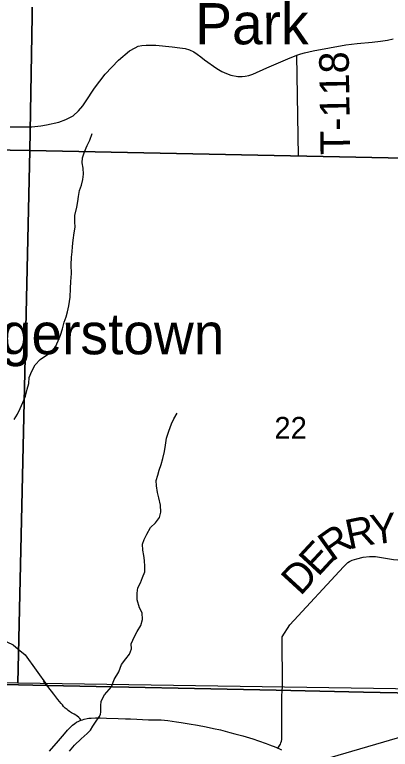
# Model space of a CAD drawing. Extents: x -7.1 to 34, y 0 to 22.
# Drawn here: x 5.689 to 6.409, y 17.646 to 19.056 of the extents above; entities that cross this region are included whole.
import ezdxf

# ---------------------------------------------------------------- set-up
doc = ezdxf.new("R2010")
doc.units = 0
for name, color, linetype in [('GM_X_Minor_River', 7, 'Continuous'), ('GM_X_Section', 7, 'Continuous'), ('GM_X_Section_Text', 7, 'Continuous'), ('GM_X_State_Route', 7, 'Continuous'), ('GM_X_Township_Road', 7, 'Continuous'), ('GM_X_Township_Road_Text', 7, 'Continuous'), ('GM_X_Unincorporated_Text', 7, 'Continuous'), ('SH_Cut_Line', 7, 'Continuous'), ('SH_Text', 7, 'Continuous')]:
    doc.layers.add(name, color=color, linetype=linetype)

msp = doc.modelspace()

# ---------------------------------------------------------------- linework, layer by layer
at = {"layer": 'GM_X_Minor_River'}
for points in [[(5.7952, 18.5136), (5.7962, 18.5303), (5.7965, 18.5436), (5.7979, 18.5588), (5.7974, 18.5755), (5.798, 18.5907), (5.7991, 18.6006), (5.8001, 18.6112), (5.8011, 18.623), (5.8033, 18.6371), (5.8051, 18.6481), (5.8046, 18.6583), (5.8045, 18.6701), (5.8082, 18.6865), (5.8104, 18.6971), (5.8114, 18.707), (5.8136, 18.7184), (5.817, 18.7287), (5.8195, 18.7397), (5.8213, 18.75), (5.8201, 18.761), (5.8185, 18.7716), (5.8192, 18.7814), (5.8229, 18.7925), (5.8281, 18.8047), (5.8329, 18.815), (5.8378, 18.8279)], [(5.6878, 18.2785), (5.6942, 18.2892), (5.6998, 18.3002), (5.7046, 18.3117), (5.7098, 18.3239), (5.7128, 18.3372), (5.7161, 18.3482), (5.7171, 18.3592), (5.722, 18.3718), (5.7283, 18.3836), (5.7377, 18.3939), (5.7479, 18.4009), (5.7593, 18.4078), (5.7675, 18.4185), (5.7724, 18.4299), (5.7772, 18.4406), (5.7805, 18.4528), (5.7839, 18.4657), (5.788, 18.476), (5.7902, 18.4855), (5.7927, 18.4973), (5.7952, 18.5136)], [(5.8747, 17.7657), (5.8797, 17.7794), (5.889, 17.7947), (5.8938, 17.8084), (5.9021, 17.8191), (5.9092, 17.8286), (5.913, 17.8385), (5.9121, 17.848), (5.9185, 17.8625), (5.9241, 17.872), (5.9312, 17.8835), (5.9341, 17.8949), (5.9333, 17.9074), (5.9286, 17.9176), (5.9239, 17.9328), (5.9238, 17.9457), (5.9249, 17.9559), (5.9305, 17.9655), (5.9338, 17.9757), (5.9383, 17.9864), (5.9386, 17.9967), (5.9377, 18.008), (5.9369, 18.0179), (5.9349, 18.0281), (5.9344, 18.0392), (5.9374, 18.0487), (5.9426, 18.059), (5.9497, 18.0712), (5.9588, 18.0807), (5.9667, 18.0907), (5.9692, 18.1009), (5.9688, 18.1146), (5.9656, 18.1283), (5.9629, 18.1389), (5.9608, 18.1514), (5.9604, 18.1616), (5.9633, 18.1719), (5.9663, 18.1814), (5.97, 18.1924), (5.9729, 18.2042), (5.9762, 18.2172), (5.9784, 18.2297), (5.9802, 18.243), (5.9843, 18.2563), (5.9899, 18.2708), (5.9943, 18.2804), (6.0007, 18.291)], [(5.7939, 17.6422), (5.8036, 17.6534), (5.8166, 17.6658), (5.8279, 17.6759), (5.8342, 17.6825), (5.8386, 17.6902), (5.8442, 17.6979), (5.8509, 17.7079), (5.8535, 17.7128), (5.8541, 17.7178), (5.8541, 17.7235), (5.8544, 17.7292), (5.855, 17.7384), (5.8611, 17.7502), (5.8747, 17.7657)]]:
    msp.add_lwpolyline(points, dxfattribs=at)
at = {"layer": 'GM_X_Section'}
for points in [[(4.7229, 19.8074), (5.7351, 19.7911), (5.7181, 18.7951), (4.6987, 18.8125)], [(6.7637, 19.7708), (6.7487, 18.7741), (5.7181, 18.7951), (5.7351, 19.7911)], [(4.6987, 18.8125), (5.7181, 18.7951), (5.6951, 17.7726), (4.6817, 17.7925)], [(5.7181, 18.7951), (6.7487, 18.7741), (6.7175, 17.7575), (5.6951, 17.7726)]]:
    msp.add_lwpolyline(points, close=True, dxfattribs=at)
at = {"layer": 'GM_X_State_Route'}
for points in [[(5.6805, 18.8406), (5.6895, 18.8408), (5.7085, 18.8405), (5.722, 18.8407), (5.7391, 18.8422), (5.7503, 18.8442), (5.774, 18.8494), (5.787, 18.8549), (5.801, 18.862), (5.8116, 18.8712), (5.8196, 18.8807), (5.8251, 18.8884), (5.8419, 18.9148), (5.8625, 18.942), (5.8878, 18.9683), (5.9091, 18.9862), (5.92, 18.9923), (5.9257, 18.9952), (5.9328, 18.9965), (5.9413, 18.9975), (5.9599, 18.9973), (5.9908, 18.9942), (6.0058, 18.9924), (6.0161, 18.9908), (6.0244, 18.9885), (6.0324, 18.9848), (6.0387, 18.9803), (6.046, 18.9747), (6.0532, 18.9692), (6.0765, 18.9524), (6.0861, 18.9467), (6.0949, 18.9429), (6.1037, 18.9397), (6.1171, 18.9371), (6.1253, 18.9373), (6.1312, 18.9378), (6.1376, 18.9392), (6.1454, 18.942), (6.1726, 18.9536), (6.2125, 18.9714), (6.2301, 18.9784), (6.2374, 18.9809), (6.2449, 18.9829), (6.2611, 18.9864), (6.3241, 18.998), (6.3453, 19.0008), (6.3746, 19.0033), (6.3905, 19.0051), (6.4036, 19.007), (6.4146, 19.0096)], [(5.7561, 17.6423), (5.773, 17.6619), (5.7848, 17.6756), (5.7906, 17.6822), (5.7938, 17.6858), (5.7976, 17.6897), (5.8002, 17.6921), (5.8042, 17.6952), (5.8079, 17.6977), (5.8119, 17.6996), (5.8148, 17.7009), (5.8168, 17.7017), (5.8189, 17.7024), (5.822, 17.7034), (5.8283, 17.7048), (5.831, 17.7052), (5.8359, 17.7056), (5.844, 17.7059), (5.8532, 17.706), (5.8648, 17.7058), (5.8872, 17.7051), (5.9014, 17.7045), (5.9112, 17.704), (5.9235, 17.7034), (5.9341, 17.7029), (5.9459, 17.7026), (5.9642, 17.7022), (5.9696, 17.702), (5.9764, 17.7015), (5.9827, 17.7009), (5.9992, 17.6986), (6.0079, 17.6973), (6.0237, 17.6947), (6.0398, 17.6918), (6.0559, 17.6888), (6.0703, 17.6859), (6.0839, 17.6828), (6.1017, 17.6783), (6.1113, 17.6757), (6.1263, 17.6714), (6.1458, 17.6656), (6.1563, 17.6621), (6.1713, 17.6569), (6.1776, 17.6546), (6.1898, 17.6497), (6.1936, 17.6481), (6.1954, 17.6472), (6.2003, 17.6448)]]:
    msp.add_lwpolyline(points, dxfattribs=at)
at = {"layer": 'GM_X_Township_Road'}
msp.add_line((6.2329, 18.7841), (6.2301, 18.9784), dxfattribs=at)
for points in [[(3.0659, 17.6986), (3.7215, 17.6707), (3.8238, 17.6717), (3.8304, 17.7952), (4.3, 17.7873), (4.5657, 17.7857), (4.7094, 17.7848), (5.0443, 17.7832), (5.0544, 17.7831), (5.1115, 17.7819), (5.5047, 17.7737), (5.7514, 17.7685), (6.1904, 17.7592), (6.3575, 17.7557), (6.7118, 17.7486), (6.7254, 18.1319), (6.7433, 18.7732), (6.7479, 19.0295), (6.7613, 19.7723), (6.7882, 20.743), (6.7921, 20.9), (2.1, 20.9)], [(5.2365, 18.4256), (5.2644, 18.3793), (5.303, 18.3221), (5.3322, 18.273), (5.3497, 18.2309), (5.3626, 18.2069), (5.3746, 18.1857), (5.4925, 18.0448), (5.6107, 17.9087), (5.6293, 17.8901), (5.6466, 17.8752), (5.6574, 17.8644), (5.6741, 17.8518), (5.6861, 17.8465), (5.6957, 17.8381), (5.7094, 17.8273), (5.7516, 17.7679)], [(6.2024, 17.7664), (6.2016, 17.8617), (6.2162, 17.8849), (6.3195, 17.9962), (6.3277, 18.004), (6.3307, 18.0063), (6.3357, 18.0086), (6.345, 18.0116), (6.3572, 18.0148), (6.3694, 18.0158), (6.3809, 18.0156), (6.4152, 18.0101), (6.4234, 18.0097), (6.4297, 18.0103), (6.5025, 18.0314), (6.5146, 18.0366), (6.552, 18.0589), (6.5663, 18.0667), (6.6032, 18.0731), (6.7016, 18.1184), (6.7052, 18.1201), (6.7079, 18.1213), (6.7121, 18.1237)], [(6.7058, 17.2839), (6.7118, 17.7486), (6.3575, 17.7557), (6.1904, 17.7592), (5.7514, 17.7685), (5.5047, 17.7737), (5.1115, 17.7819), (5.0544, 17.7831), (5.0443, 17.7832), (4.7094, 17.7848), (4.5657, 17.7857), (4.3, 17.7873), (3.8304, 17.7952), (3.8238, 17.6717), (3.7215, 17.6707), (3.0659, 17.6986), (2.7886, 17.7105), (2.5551, 17.7155), (2.1, 17.7253), (2.1, 14.1)], [(5.8168, 17.7017), (5.8139, 17.705), (5.8122, 17.7067), (5.8084, 17.7098), (5.8065, 17.7111), (5.8029, 17.7132), (5.7982, 17.7159), (5.7942, 17.7184), (5.7919, 17.72), (5.7895, 17.7219), (5.786, 17.7248), (5.7829, 17.7282), (5.7807, 17.731), (5.7782, 17.7339), (5.7753, 17.7375), (5.772, 17.7415), (5.764, 17.7513), (5.7527, 17.766), (5.7471, 17.7732), (5.7445, 17.7767)], [(6.1936, 17.6481), (6.1962, 17.652), (6.1984, 17.6559), (6.1994, 17.6581), (6.2004, 17.6614), (6.201, 17.6648), (6.2013, 17.6683), (6.2014, 17.6735), (6.2011, 17.7175), (6.2012, 17.7335), (6.2014, 17.7479), (6.2019, 17.758), (6.2024, 17.7664)]]:
    msp.add_lwpolyline(points, dxfattribs=at)
at = {"layer": 'SH_Cut_Line'}
for points in [[(8.9, 17.7079), (8.9, 20.9), (2.1, 20.9), (2.1, 17.7253), (2.5551, 17.7155), (2.7886, 17.7105), (3.0659, 17.6986), (3.7215, 17.6707), (3.8238, 17.6717), (3.8304, 17.7952), (4.3, 17.7873), (4.5657, 17.7857), (4.7094, 17.7848), (5.0443, 17.7832), (5.0544, 17.7831), (5.1115, 17.7819), (5.5047, 17.7737), (5.7514, 17.7685), (6.1904, 17.7592), (6.3575, 17.7557), (6.7118, 17.7486), (7.7202, 17.7285), (8.4472, 17.7189), (8.6668, 17.7136)], [(2.1, 17.7253), (2.1, 14.1), (8.9, 14.1), (8.9, 17.7079), (8.6668, 17.7136), (8.4472, 17.7189), (7.7202, 17.7285), (6.7118, 17.7486), (6.3575, 17.7557), (6.1904, 17.7592), (5.7514, 17.7685), (5.5047, 17.7737), (5.1115, 17.7819), (5.0544, 17.7831), (5.0443, 17.7832), (4.7094, 17.7848), (4.5657, 17.7857), (4.3, 17.7873), (3.8304, 17.7952), (3.8238, 17.6717), (3.7215, 17.6707), (3.0659, 17.6986), (2.7886, 17.7105), (2.5551, 17.7155)]]:
    msp.add_lwpolyline(points, close=True, dxfattribs=at)
at = {"layer": 'SH_Text'}
msp.add_lwpolyline([(5.1887, 17.3067), (9.3652, 18.5286), (9.3652, 18.2766)], close=True, dxfattribs=at)

# ---------------------------------------------------------------- texts
at = {"layer": 'GM_X_Section_Text'}
msp.add_text('22', height=0.04186, rotation=0, dxfattribs=at).set_placement((6.1869, 18.2419))
at = {"layer": 'GM_X_Township_Road_Text'}
for s, height, rotation, p in [('T-118', 0.05682, 90.8431, (6.3322, 18.7872)), ('R', 0.0568, 11.7382, (6.3296, 18.0292)), ('Y', 0.0568, 6.4979, (6.3739, 18.0385)), ('R', 0.0568, 35.4569, (6.2972, 18.0046)), ('E', 0.0568, 47.2036, (6.2706, 17.9755)), ('D', 0.0568, 47.3975, (6.2368, 17.9387))]:
    msp.add_text(s, height=height, rotation=rotation, dxfattribs=at).set_placement(p)
at = {"layer": 'GM_X_Unincorporated_Text'}
for s, height, p in [('Park', 0.07898, (6.0353, 18.999)), ('New Hagerstown', 0.078977, (5.2869, 18.404))]:
    msp.add_text(s, height=height, rotation=0, dxfattribs=at).set_placement(p)

doc.saveas('drawing.dxf')
